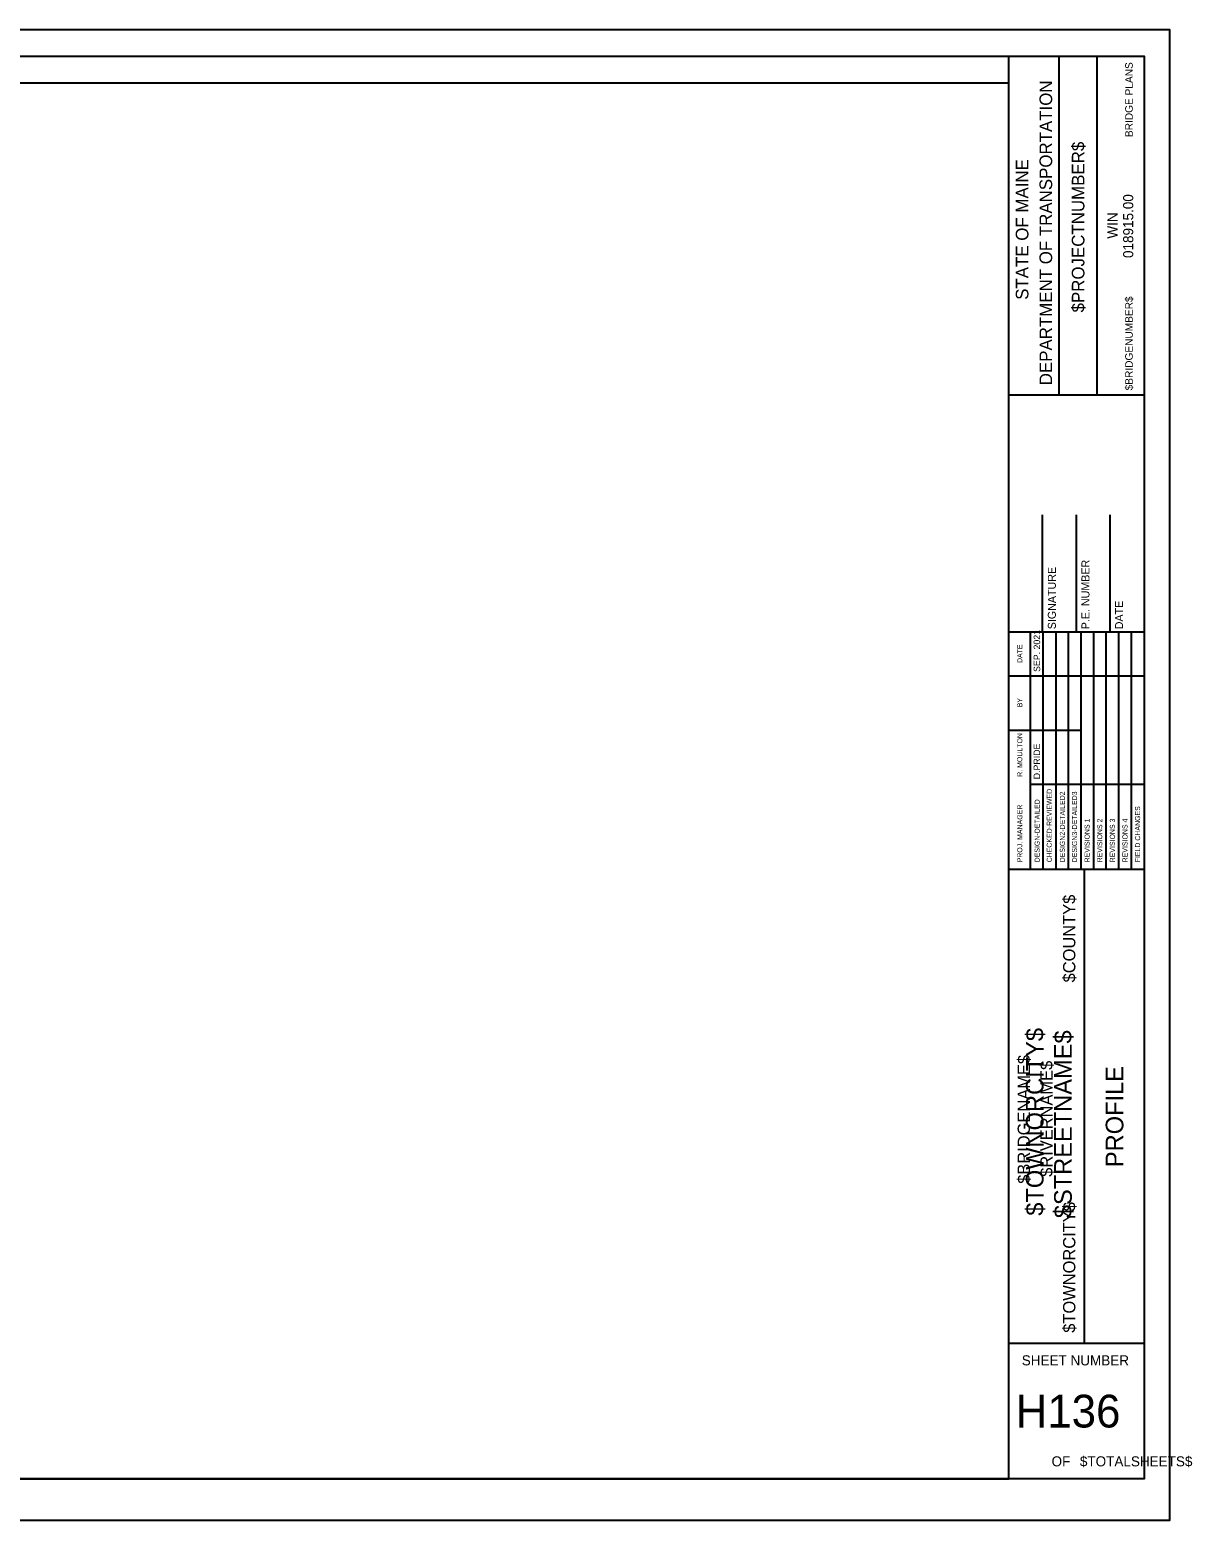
# Model space of a CAD drawing. Extents: x 10878 to 11736, y 9985 to 10535.
# Drawn here: x 11307 to 11736, y 9985 to 10535 of the extents above; entities that cross this region are included whole.
import ezdxf

# ---------------------------------------------------------------- set-up
doc = ezdxf.new("R2010")
doc.units = 0
for name, color, linetype in [('BORDER', 7, 'Continuous'), ('BRIDGE_TITLE', 7, 'Continuous'), ('CLIPS', 7, 'Continuous'), ('HIGHWAY_TITLE', 7, 'Continuous'), ('PLOT BOUNDARY', 7, 'Continuous')]:
    doc.layers.add(name, color=color, linetype=linetype)

msp = doc.modelspace()

# ---------------------------------------------------------------- linework, layer by layer
at = {"layer": 'BORDER'}
for p, q in [((11668.31, 10000), (11668.31, 10525)), ((11686.96, 10399.99), (11686.96, 10524.99)), ((11700.93, 10399.99), (11700.93, 10524.99)), ((11668.32, 10399.97), (11718.31, 10399.97)), ((11680.81, 10312.51), (11680.81, 10355.75)), ((11693.31, 10312.51), (11693.31, 10355.75)), ((11705.81, 10312.51), (11705.81, 10355.75)), ((11668.31, 10312.51), (11718.31, 10312.51)), ((11668.31, 10225.01), (11718.31, 10225.01)), ((11696.27, 10050.01), (11696.27, 10225.01)), ((11668.31, 10050.01), (11718.31, 10050.01))]:
    msp.add_line(p, q, dxfattribs=at)
msp.add_lwpolyline([(10918.31, 10525), (11718.31, 10525), (11718.31, 10000), (10918.31, 10000)], close=True, dxfattribs=at)
for points in [[(11676.39, 10296.26), (11676.39, 10312.51)], [(11681.05, 10225.03), (11681.05, 10312.51)], [(11685.71, 10312.51), (11685.71, 10225.03)], [(11690.37, 10225.03), (11690.37, 10312.51)], [(11695.03, 10225.03), (11695.03, 10312.51)], [(11699.69, 10225.03), (11699.69, 10312.51)], [(11704.34, 10225.03), (11704.34, 10312.51)], [(11709, 10225.03), (11709, 10312.51)], [(11713.66, 10225.03), (11713.66, 10312.51)], [(11676.39, 10225.03), (11676.39, 10308.98)], [(11668.31, 10296.26), (11718.31, 10296.26)], [(11668.31, 10276.26), (11676.39, 10276.26)], [(11676.39, 10276.26), (11695.02, 10276.26)], [(11676.39, 10256.26), (11718.31, 10256.26)]]:
    msp.add_lwpolyline(points, dxfattribs=at)
at = {"layer": 'CLIPS'}
msp.add_lwpolyline([(10918.31, 10000), (11668.31, 10000), (11668.31, 10515), (10918.31, 10515)], close=True, dxfattribs=at)
at = {"layer": 'PLOT BOUNDARY'}
msp.add_lwpolyline([(10877.85, 9984.7), (11727.85, 9984.7), (11727.85, 10534.7), (10877.85, 10534.7)], close=True, dxfattribs=at)

# ---------------------------------------------------------------- texts
at = {"layer": 'BORDER'}
for s, height, p in [('DEPARTMENT OF TRANSPORTATION', 4.6588, (11684.35, 10403.53)), ('$PROJECTNUMBER$', 4.6588, (11696.27, 10430.4)), ('STATE OF MAINE', 4.6588, (11675.59, 10435.06)), ('018915.00', 3.726, (11714.29, 10450.49)), ('WIN', 3.726, (11708.5, 10457.65)), ('SIGNATURE', 2.953, (11685.72, 10313.48)), ('P.E. NUMBER', 2.9528, (11698.12, 10313.48)), ('DATE', 2.953, (11710.52, 10313.48)), ('SEP. 2021', 2.423, (11679.93, 10297.74)), ('DATE', 1.857, (11673.34, 10301.04)), ('BY', 1.857, (11673.34, 10284.69)), ('R. MOULTON', 1.864, (11673.34, 10259.03)), ('D.PRIDE', 2.423, (11679.93, 10258.13)), ('CHECKED-REVIEWED', 1.8637, (11684.22, 10227.46)), ('DESIGN2-DETAILED2', 1.8637, (11689.06, 10227.46)), ('DESIGN3-DETAILED3', 1.8637, (11693.54, 10227.46)), ('PROJ. MANAGER', 1.8637, (11673.34, 10227.46)), ('DESIGN-DETAILED', 1.8637, (11679.75, 10227.46)), ('FIELD CHANGES', 1.8637, (11716.83, 10227.46)), ('REVISIONS 1', 1.8637, (11698.19, 10227.46)), ('REVISIONS 2', 1.8637, (11702.85, 10227.46)), ('REVISIONS 3', 1.8637, (11707.51, 10227.46)), ('REVISIONS 4', 1.8637, (11712.17, 10227.46)), ('PROFILE', 6.521, (11710.64, 10115))]:
    msp.add_text(s, height=height, rotation=90, dxfattribs=at).set_placement(p)
for s, height, p in [('SHEET NUMBER', 3.7264, (11673.14, 10041.83)), ('H136', 12.097, (11670.89, 10018.91)), ('OF', 3.726, (11684.15, 10004.56)), ('$TOTALSHEETS$', 3.7264, (11694.6, 10004.56))]:
    msp.add_text(s, height=height, dxfattribs=at).set_placement(p)
at = {"layer": 'BRIDGE_TITLE'}
for s, height, p in [('BRIDGE PLANS', 2.795, (11714.11, 10495.12)), ('$BRIDGENUMBER$', 2.795, (11714.11, 10401.65)), ('$COUNTY$', 4.536, (11692.92, 10183.17)), ('$BRIDGENAME$', 4.5358, (11676.15, 10108.86)), ('$RIVERNAME$', 4.5358, (11684.53, 10111.43)), ('$TOWNORCITY$', 4.5358, (11692.92, 10053.88))]:
    msp.add_text(s, height=height, rotation=90, dxfattribs=at).set_placement(p)
at = {"layer": 'HIGHWAY_TITLE'}
for s, p in [('$TOWNORCITY$', (11681.18, 10097.06)), ('$STREETNAME$', (11691.61, 10096.16))]:
    msp.add_text(s, height=6.5214, rotation=90, dxfattribs=at).set_placement(p)

doc.saveas('drawing.dxf')
